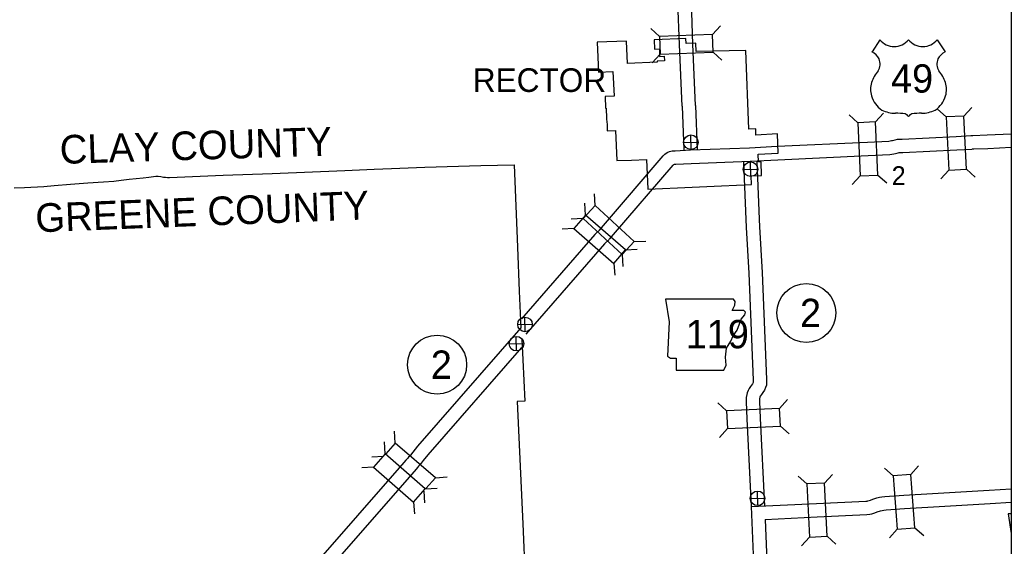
# Model space of a CAD drawing. Extents: x -0.3 to 2.65, y 0 to 1.9.
# Drawn here: x 0.1338 to 0.3417, y 0.6874 to 0.7976 of the extents above; entities that cross this region are included whole.
import ezdxf

# ---------------------------------------------------------------- set-up
doc = ezdxf.new("R2010")
doc.units = 0
for name, color, linetype in [('DSN_DRFT_DNC', 7, 'Continuous'), ('Level 10', 7, 'Continuous'), ('Level 21', 7, 'Continuous'), ('Level 22', 7, 'Continuous'), ('Level 23', 7, 'Continuous'), ('Level 26', 7, 'Continuous'), ('Level 27', 7, 'Continuous'), ('Level 38', 7, 'Continuous'), ('Level 39', 7, 'Continuous'), ('Level 59', 7, 'Continuous'), ('Level 6', 7, 'Continuous')]:
    doc.layers.add(name, color=color, linetype=linetype)

msp = doc.modelspace()

# ---------------------------------------------------------------- linework, layer by layer
at = {"layer": 'DSN_DRFT_DNC'}
msp.add_lwpolyline([(0.04166666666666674, 0.8750000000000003), (0.34166666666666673, 0.8750000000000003), (0.34166666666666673, 0.541666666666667), (0.04166666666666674, 0.541666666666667)], close=True, dxfattribs=at)
at = {"layer": 'Level 21'}
for p, q in [((0.3370799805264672, 0.6990997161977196), (0.34166666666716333, 0.6993791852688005)), ((0.3372510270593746, 0.6962924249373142), (0.34166666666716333, 0.6965614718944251))]:
    msp.add_line(p, q, dxfattribs=at)
for points in [[(0.2726580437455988, 0.7795435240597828), (0.272141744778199, 0.7924518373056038), (0.2718029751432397, 0.8012743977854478)], [(0.27546828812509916, 0.7796559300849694), (0.2749520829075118, 0.7925619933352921), (0.27461354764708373, 0.8013784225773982)], [(0.2726580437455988, 0.7795435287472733), (0.27302461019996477, 0.7703786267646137)], [(0.27546828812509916, 0.7796559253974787), (0.27583518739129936, 0.7704826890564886)], [(0.2855585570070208, 0.7678157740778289), (0.28611326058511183, 0.7541116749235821)], [(0.28836677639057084, 0.7679783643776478), (0.28892345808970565, 0.7542254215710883)], [(0.28611416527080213, 0.754092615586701), (0.2866308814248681, 0.7445370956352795), (0.2875687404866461, 0.7221638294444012), (0.28758491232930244, 0.721813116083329), (0.2875783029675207, 0.7217379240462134), (0.2875546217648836, 0.7216719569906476), (0.2874399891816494, 0.721405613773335), (0.28725100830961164, 0.7211120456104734), (0.28702914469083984, 0.7207873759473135), (0.28673953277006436, 0.7203925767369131), (0.2864928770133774, 0.7199808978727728), (0.28630370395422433, 0.7195135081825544), (0.2862182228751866, 0.7191054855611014), (0.28611414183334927, 0.7184821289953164), (0.2861087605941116, 0.7176244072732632), (0.2862352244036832, 0.714059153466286), (0.28711901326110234, 0.6956487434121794)], [(0.28892255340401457, 0.7542444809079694), (0.28944019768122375, 0.7446719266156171), (0.29037851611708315, 0.7222875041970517), (0.29040309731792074, 0.7217545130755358), (0.29034817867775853, 0.7211296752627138), (0.29017236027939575, 0.7206399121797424), (0.289931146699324, 0.7200794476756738), (0.28959493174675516, 0.7195571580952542), (0.2893247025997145, 0.7191617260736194), (0.2890847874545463, 0.7188346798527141), (0.2890178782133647, 0.7187230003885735), (0.28900495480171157, 0.718691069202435), (0.28898280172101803, 0.7185853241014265), (0.28892517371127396, 0.7182401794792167), (0.28892156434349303, 0.7176654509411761), (0.2890453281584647, 0.7141764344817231), (0.2899288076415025, 0.6957724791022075)], [(0.28712597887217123, 0.6956467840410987), (0.30087906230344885, 0.6963295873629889), (0.3112075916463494, 0.6967827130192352), (0.3114881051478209, 0.6968142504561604), (0.31164821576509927, 0.6968562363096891), (0.31216593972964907, 0.6970312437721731), (0.31268421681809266, 0.6972220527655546), (0.3135328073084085, 0.697480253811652), (0.3140553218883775, 0.6976040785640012), (0.3145580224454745, 0.6976969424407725), (0.31518413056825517, 0.6977582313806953), (0.3191289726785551, 0.6980559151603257), (0.32518447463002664, 0.6984041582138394), (0.33708341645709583, 0.6990999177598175)], [(0.2900566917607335, 0.6929763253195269), (0.30101042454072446, 0.6935201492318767), (0.31142660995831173, 0.6939771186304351), (0.3120046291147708, 0.6940421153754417), (0.31245621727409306, 0.6941605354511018), (0.3131022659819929, 0.694378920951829), (0.3135801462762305, 0.6945548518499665), (0.3142671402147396, 0.6947638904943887), (0.31463539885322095, 0.6948511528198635), (0.3149511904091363, 0.6949094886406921), (0.3154269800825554, 0.6949560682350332), (0.3193155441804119, 0.6952495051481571), (0.3253472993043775, 0.6955963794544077), (0.33724759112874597, 0.6962922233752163)], [(0.28712597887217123, 0.6956467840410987), (0.28799091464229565, 0.6755768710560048), (0.2882637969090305, 0.6694553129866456)], [(0.2900561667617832, 0.6929763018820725), (0.2908007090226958, 0.6757000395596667), (0.2910734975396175, 0.6695805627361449)]]:
    msp.add_lwpolyline(points, dxfattribs=at)
at = {"layer": 'Level 22'}
msp.add_lwpolyline([(0.2692183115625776, 0.739145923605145), (0.26993203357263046, 0.7343877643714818), (0.26961482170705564, 0.7271712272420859), (0.2702492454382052, 0.7267747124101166), (0.27143878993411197, 0.7267747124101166), (0.27143878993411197, 0.7242370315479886), (0.2814309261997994, 0.7242370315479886), (0.28190673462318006, 0.7252679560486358), (0.281748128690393, 0.7269333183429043), (0.28198603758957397, 0.7288365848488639), (0.2828583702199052, 0.730343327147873), (0.283413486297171, 0.7314535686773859), (0.28420651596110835, 0.7326431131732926), (0.2846823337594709, 0.7339119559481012), (0.28507884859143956, 0.734942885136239), (0.2857925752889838, 0.7358152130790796), (0.2859511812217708, 0.7363703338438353), (0.285633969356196, 0.7367668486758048), (0.28317558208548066, 0.7367668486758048), (0.2837306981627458, 0.7378770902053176), (0.2838100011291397, 0.7385908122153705), (0.2834811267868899, 0.7391389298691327)], close=True, dxfattribs=at)
msp.add_lwpolyline([(0.3416666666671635, 0.6941333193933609), (0.3410443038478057, 0.6941336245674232), (0.34166666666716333, 0.6899845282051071)], dxfattribs=at)
at = {"layer": 'Level 23'}
for points in [[(0.16086406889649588, 0.7646429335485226), (0.16235440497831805, 0.7648591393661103), (0.16281201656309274, 0.7649075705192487), (0.16340873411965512, 0.7647831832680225), (0.16397693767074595, 0.7646669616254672), (0.16439109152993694, 0.7646381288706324), (0.16474906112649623, 0.7646068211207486), (0.1651713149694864, 0.7646066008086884), (0.17642949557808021, 0.7650652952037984), (0.18670563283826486, 0.7654524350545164), (0.201991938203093, 0.7660604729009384), (0.20809737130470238, 0.766339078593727), (0.2117773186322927, 0.7665107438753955), (0.21871064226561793, 0.7667410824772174), (0.23047998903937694, 0.7670998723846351), (0.2374720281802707, 0.7672762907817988), (0.23817552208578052, 0.7500029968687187)], [(0.13264490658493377, 0.7624142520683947), (0.1347763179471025, 0.7625336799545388), (0.13887330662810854, 0.7626916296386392), (0.1409924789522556, 0.7628953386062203), (0.14442978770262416, 0.7631720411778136), (0.14804485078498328, 0.7634547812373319), (0.1513627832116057, 0.7636615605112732), (0.15351001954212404, 0.7638662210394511), (0.155048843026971, 0.7640596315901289), (0.15674606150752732, 0.7642772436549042), (0.15965947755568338, 0.7645361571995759), (0.16086406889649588, 0.7646429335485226)], [(0.23817552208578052, 0.7500029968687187), (0.23849075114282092, 0.740757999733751), (0.23887282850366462, 0.7330998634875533)], [(0.23907959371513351, 0.7307290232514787), (0.23972831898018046, 0.7177264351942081), (0.23808092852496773, 0.717649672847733), (0.23929112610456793, 0.6920143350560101), (0.2397868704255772, 0.6804493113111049), (0.24017406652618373, 0.6714418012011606), (0.24039522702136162, 0.6670523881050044), (0.2650557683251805, 0.6682768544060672), (0.2874486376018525, 0.6694059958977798)]]:
    msp.add_lwpolyline(points, dxfattribs=at)
at = {"layer": 'Level 26'}
for p, q in [((0.31411140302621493, 0.7934594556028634), (0.3124887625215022, 0.7909500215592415)), ((0.32617612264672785, 0.7934594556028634), (0.3277987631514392, 0.7909500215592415))]:
    msp.add_line(p, q, dxfattribs=at)
for centre, radius, start, end in [((0.31713325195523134, 0.7960018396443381), 0.0039490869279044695, 220.0750416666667, 319.6701166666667), ((0.3231542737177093, 0.7960018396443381), 0.003949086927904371, 220.32988333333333, 319.92495833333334), ((0.31036849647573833, 0.7873070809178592), 0.00421571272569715, 30.780902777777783, 59.98827222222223), ((0.329919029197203, 0.7873070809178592), 0.00421571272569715, 120.01172777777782, 149.21909722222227), ((0.31129612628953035, 0.7884188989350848), 0.002889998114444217, 328.8104583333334, 21.210766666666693), ((0.32899139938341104, 0.7884188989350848), 0.0028899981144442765, 158.78923333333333, 211.18954166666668), ((0.3188533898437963, 0.7824951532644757), 0.006742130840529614, 138.9564777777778, 162.69134722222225), ((0.32143413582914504, 0.7824951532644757), 0.006742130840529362, 17.308652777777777, 41.04352222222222), ((0.31662772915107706, 0.7830475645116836), 0.004454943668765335, 160.95764444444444, 197.38185555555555), ((0.3236597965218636, 0.7830475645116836), 0.004454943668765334, 342.61814444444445, 19.042355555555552), ((0.3173529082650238, 0.7830602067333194), 0.005154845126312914, 195.10743055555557, 237.13119444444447), ((0.3229346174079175, 0.7830602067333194), 0.005154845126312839, 302.8688055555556, 344.89256944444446), ((0.31744894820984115, 0.7846837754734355), 0.00661920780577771, 244.07708333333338, 269.5778527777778), ((0.3176020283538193, 0.7659415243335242), 0.01212490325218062, 81.19415555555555, 90.953875), ((0.31911823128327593, 0.7768125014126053), 0.0011618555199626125, 28.034222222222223, 72.98637222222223), ((0.3211692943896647, 0.7768125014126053), 0.0011618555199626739, 107.01362777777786, 151.96577777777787), ((0.32268549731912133, 0.7659415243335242), 0.012124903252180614, 89.04612500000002, 98.80584444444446), ((0.3228385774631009, 0.7846837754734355), 0.0066192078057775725, 270.42214722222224, 295.92291666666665)]:
    msp.add_arc(centre, radius, start, end, dxfattribs=at)
at = {"layer": 'Level 27'}
for points in [[(0.2553620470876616, 0.7535983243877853), (0.25622183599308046, 0.7545319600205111), (0.26872967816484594, 0.7691348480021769), (0.2690859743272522, 0.769470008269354), (0.26954757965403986, 0.7698277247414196), (0.27006157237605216, 0.7700253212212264), (0.27061111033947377, 0.7701702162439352), (0.27122311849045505, 0.7702095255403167), (0.27442531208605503, 0.7703791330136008), (0.286837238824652, 0.7708321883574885), (0.2925970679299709, 0.7711425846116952), (0.3115590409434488, 0.7720068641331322), (0.3159874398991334, 0.7722486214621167), (0.31656468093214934, 0.7723206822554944), (0.31678781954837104, 0.7723729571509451), (0.3173346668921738, 0.7725022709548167), (0.3178282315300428, 0.7726115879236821), (0.31880820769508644, 0.7726655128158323), (0.3301031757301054, 0.7732200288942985), (0.33330448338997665, 0.7733800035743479)], [(0.33323498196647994, 0.7733748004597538), (0.3336395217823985, 0.7734151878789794), (0.3366521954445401, 0.773513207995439), (0.34166666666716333, 0.7737541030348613)], [(0.25743091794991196, 0.7516930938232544), (0.2583249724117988, 0.7526639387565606), (0.2707671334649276, 0.7671901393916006), (0.27091506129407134, 0.7673292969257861), (0.27093940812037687, 0.7673481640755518), (0.2710640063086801, 0.7673810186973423), (0.27138764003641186, 0.7674018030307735), (0.2745509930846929, 0.7675693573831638), (0.2869642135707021, 0.7680224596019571), (0.29273677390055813, 0.7683335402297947), (0.3116997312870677, 0.7691978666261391), (0.31623860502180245, 0.7694456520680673), (0.31706102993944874, 0.7695483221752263), (0.31743219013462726, 0.7696352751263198), (0.3179623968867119, 0.7697606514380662), (0.31821212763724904, 0.769815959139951), (0.31895442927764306, 0.7698568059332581), (0.3302423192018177, 0.7704109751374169), (0.33344485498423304, 0.7705710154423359)], [(0.33351435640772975, 0.7705762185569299), (0.33382514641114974, 0.7706072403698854), (0.33676540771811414, 0.7707029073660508), (0.34166666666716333, 0.7709383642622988)], [(0.25541840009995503, 0.7536560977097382), (0.2543737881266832, 0.7526448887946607), (0.2389892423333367, 0.735011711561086)], [(0.2573745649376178, 0.7516353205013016), (0.2564151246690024, 0.7507065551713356), (0.23990041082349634, 0.7317780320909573)], [(0.23887062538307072, 0.7330997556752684), (0.21717789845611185, 0.7082877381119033), (0.2162002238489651, 0.7070598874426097), (0.215723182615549, 0.7064492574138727), (0.21556655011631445, 0.7062432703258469), (0.21533925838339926, 0.7059993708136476), (0.21507742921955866, 0.7057086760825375), (0.2147759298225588, 0.7053534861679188), (0.21434821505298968, 0.7048591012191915), (0.16674346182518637, 0.6504592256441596), (0.1664469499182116, 0.6500967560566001), (0.16619319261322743, 0.6497620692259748), (0.16608823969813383, 0.6496233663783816), (0.16590203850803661, 0.6494166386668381), (0.1656448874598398, 0.6489837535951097), (0.16548952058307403, 0.648699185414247), (0.1653403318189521, 0.6484147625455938), (0.1650963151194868, 0.6479254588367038), (0.16506586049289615, 0.6474507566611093)], [(0.23901848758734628, 0.7289958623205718), (0.21933782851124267, 0.7064852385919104), (0.21840854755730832, 0.7053181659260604), (0.21795083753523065, 0.7047322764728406), (0.2177200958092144, 0.7044288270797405), (0.21741306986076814, 0.7040993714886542), (0.217194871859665, 0.7038571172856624), (0.21691155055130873, 0.7035233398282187), (0.21646997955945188, 0.7030129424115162), (0.16889076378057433, 0.6486422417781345), (0.16865672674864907, 0.6483561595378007), (0.16843516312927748, 0.648063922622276), (0.16825847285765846, 0.6478304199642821), (0.1681779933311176, 0.6477410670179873), (0.16808897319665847, 0.6475912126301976), (0.1679692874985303, 0.6473719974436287), (0.1678665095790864, 0.6471760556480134), (0.16783376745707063, 0.6466657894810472)]]:
    msp.add_lwpolyline(points, dxfattribs=at)
at = {"layer": 'Level 38'}
for p, q in [((0.27903702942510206, 0.7945842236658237), (0.2807157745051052, 0.7964028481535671)), ((0.2679084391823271, 0.7941391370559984), (0.26608981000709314, 0.7958178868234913)), ((0.26805679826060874, 0.7904296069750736), (0.2663780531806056, 0.7886109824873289)), ((0.2791853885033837, 0.7908746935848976), (0.28100401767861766, 0.7891959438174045)), ((0.30952150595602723, 0.776080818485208), (0.30769354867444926, 0.7777494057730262)), ((0.3132301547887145, 0.7762498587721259), (0.3148987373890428, 0.778077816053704)), ((0.32804567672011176, 0.7772865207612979), (0.32621188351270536, 0.7789486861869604)), ((0.3317537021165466, 0.7774685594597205), (0.33341586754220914, 0.7793023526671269)), ((0.3100286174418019, 0.7649548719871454), (0.3083600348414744, 0.7631269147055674)), ((0.31373726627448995, 0.7651239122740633), (0.3155652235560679, 0.7634553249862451)), ((0.328591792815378, 0.7661624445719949), (0.3269296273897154, 0.7643286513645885)), ((0.3322998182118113, 0.7663444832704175), (0.33413361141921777, 0.7646823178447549)), ((0.2544344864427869, 0.7587357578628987), (0.25433266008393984, 0.7612086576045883)), ((0.25241864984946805, 0.7567354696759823), (0.25225047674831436, 0.7592047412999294)), ((0.2519195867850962, 0.756004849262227), (0.24944668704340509, 0.7559030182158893)), ((0.24997796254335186, 0.7539380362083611), (0.24750869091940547, 0.7537698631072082)), ((0.2626272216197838, 0.7511910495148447), (0.26510012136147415, 0.7512928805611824)), ((0.2601123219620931, 0.748460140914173), (0.2602141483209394, 0.7459872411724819)), ((0.2608109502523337, 0.7494134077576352), (0.2632802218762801, 0.7495815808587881)), ((0.2583702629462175, 0.746615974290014), (0.2585384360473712, 0.744146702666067)), ((0.2819889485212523, 0.7157048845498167), (0.28015696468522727, 0.7173690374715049)), ((0.2931135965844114, 0.716238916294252), (0.2947777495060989, 0.7180709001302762)), ((0.21252024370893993, 0.7089765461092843), (0.21234176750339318, 0.711445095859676)), ((0.2821669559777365, 0.7119966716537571), (0.28050280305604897, 0.7101646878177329)), ((0.2932916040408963, 0.7125307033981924), (0.29512358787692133, 0.7108665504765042)), ((0.2104460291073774, 0.7067206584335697), (0.21028152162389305, 0.7091901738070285)), ((0.21252024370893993, 0.7089765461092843), (0.21054297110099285, 0.7066910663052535)), ((0.2209430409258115, 0.7016895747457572), (0.21252024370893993, 0.7089765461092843)), ((0.21009125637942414, 0.7061689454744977), (0.20762270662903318, 0.7059904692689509)), ((0.2080011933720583, 0.7039268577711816), (0.20553167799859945, 0.7037623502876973)), ((0.31695224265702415, 0.7020659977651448), (0.3150754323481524, 0.7036794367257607)), ((0.32065422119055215, 0.7023453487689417), (0.3222676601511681, 0.7042221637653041)), ((0.21897784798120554, 0.6994180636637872), (0.2209430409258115, 0.7016895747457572)), ((0.2209430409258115, 0.7016895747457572), (0.22341159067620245, 0.7018680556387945)), ((0.29881463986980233, 0.7003947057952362), (0.2969799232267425, 0.7020558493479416)), ((0.30252256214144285, 0.7005787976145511), (0.3041837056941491, 0.7024135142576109)), ((0.2185140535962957, 0.6988819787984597), (0.21869252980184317, 0.6964134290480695)), ((0.21882744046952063, 0.6993861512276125), (0.22129695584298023, 0.6995506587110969)), ((0.21638260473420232, 0.6965923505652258), (0.21654711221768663, 0.6941228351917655)), ((0.3177902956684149, 0.6909600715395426), (0.316176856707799, 0.6890832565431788)), ((0.3214922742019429, 0.6912394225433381), (0.3233690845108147, 0.6896259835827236)), ((0.29936692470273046, 0.6892709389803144), (0.2977057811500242, 0.6874362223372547)), ((0.303074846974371, 0.6894550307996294), (0.3049095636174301, 0.6877938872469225))]:
    msp.add_line(p, q, dxfattribs=at)
for points in [[(0.26805679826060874, 0.7904296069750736), (0.2791853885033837, 0.7908746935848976), (0.27903702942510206, 0.7945842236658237), (0.2679084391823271, 0.7941391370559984)], [(0.32804567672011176, 0.7772865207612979), (0.328591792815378, 0.7661624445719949), (0.3322998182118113, 0.7663444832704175), (0.3317537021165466, 0.7774685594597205)], [(0.30952150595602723, 0.776080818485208), (0.3100286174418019, 0.7649548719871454), (0.31373726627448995, 0.7651239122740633), (0.3132301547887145, 0.7762498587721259)], [(0.2519195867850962, 0.756004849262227), (0.2601123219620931, 0.748460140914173), (0.2626272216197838, 0.7511910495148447), (0.2544344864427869, 0.7587357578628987)], [(0.24997796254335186, 0.7539380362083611), (0.2583702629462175, 0.746615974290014), (0.2608109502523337, 0.7494134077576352), (0.25241864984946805, 0.7567354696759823)], [(0.2821669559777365, 0.7119966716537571), (0.2932916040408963, 0.7125307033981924), (0.2931135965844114, 0.716238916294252), (0.2819889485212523, 0.7157048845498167)], [(0.2080011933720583, 0.7039268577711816), (0.21638260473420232, 0.6965923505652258), (0.21882744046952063, 0.6993861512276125), (0.2104460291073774, 0.7067206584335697)], [(0.29881463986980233, 0.7003947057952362), (0.29936692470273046, 0.6892709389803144), (0.303074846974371, 0.6894550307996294), (0.30252256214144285, 0.7005787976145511)], [(0.31695224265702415, 0.7020659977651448), (0.3177902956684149, 0.6909600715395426), (0.3214922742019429, 0.6912394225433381), (0.32065422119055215, 0.7023453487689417)]]:
    msp.add_lwpolyline(points, close=True, dxfattribs=at)
at = {"layer": 'Level 39'}
for p, q in [((0.2745605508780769, 0.7704648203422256), (0.274490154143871, 0.7735161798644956)), ((0.27299967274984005, 0.7719553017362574), (0.27605103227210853, 0.7720256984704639)), ((0.28706858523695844, 0.7648192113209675), (0.28699818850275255, 0.767870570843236)), ((0.2855077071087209, 0.7663096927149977), (0.2885590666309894, 0.7663800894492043)), ((0.23820793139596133, 0.7337788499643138), (0.24125929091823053, 0.7338492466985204)), ((0.23976880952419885, 0.7322883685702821), (0.239698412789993, 0.7353397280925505)), ((0.2364096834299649, 0.7297482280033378), (0.2394610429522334, 0.7298186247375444)), ((0.23797056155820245, 0.7282577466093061), (0.23790016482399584, 0.7313091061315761)), ((0.2885318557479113, 0.6958623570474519), (0.28846145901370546, 0.6989137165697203)), ((0.2869709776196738, 0.6973528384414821), (0.290022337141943, 0.6974232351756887))]:
    msp.add_line(p, q, dxfattribs=at)
for centre in [(0.2745253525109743, 0.7719905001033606), (0.28703338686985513, 0.766344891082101), (0.2397336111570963, 0.7338140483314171), (0.23793536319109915, 0.7297834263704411), (0.2884966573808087, 0.6973880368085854)]:
    msp.add_circle(centre, 0.0015260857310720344, dxfattribs=at)
at = {"layer": 'Level 59'}
for centre in [(0.29871051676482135, 0.7362204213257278), (0.22131766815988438, 0.7253853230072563)]:
    msp.add_circle(centre, 0.006187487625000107, dxfattribs=at)
at = {"layer": 'Level 6'}
msp.add_lwpolyline([(0.2747822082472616, 0.7625891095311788), (0.2809218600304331, 0.7628742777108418), (0.28722363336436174, 0.7631669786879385), (0.2871460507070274, 0.76493968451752), (0.2893254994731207, 0.7649904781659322), (0.2892194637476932, 0.7678947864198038), (0.2886962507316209, 0.7678825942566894), (0.28861531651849, 0.7694971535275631), (0.29284777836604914, 0.7696951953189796), (0.29264925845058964, 0.77371811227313), (0.28814770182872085, 0.7734568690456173), (0.28813599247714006, 0.7747717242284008), (0.2866989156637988, 0.7747057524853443), (0.28606498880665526, 0.7912303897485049), (0.2756419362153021, 0.7910293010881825), (0.27557122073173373, 0.7927569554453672), (0.2735106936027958, 0.7926669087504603), (0.273467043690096, 0.7937232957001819), (0.2668214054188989, 0.7934411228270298), (0.26690387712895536, 0.7915140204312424), (0.2679121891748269, 0.7915593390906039), (0.2679617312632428, 0.7899493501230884), (0.2689463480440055, 0.7899936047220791), (0.2689911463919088, 0.7890640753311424), (0.2674168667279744, 0.7890005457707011), (0.26742597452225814, 0.7887877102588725), (0.26119275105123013, 0.7885039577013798), (0.26098515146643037, 0.7931933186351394), (0.25486854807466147, 0.7929220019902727), (0.2551368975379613, 0.7866927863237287), (0.25818558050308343, 0.7868201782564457), (0.2584002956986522, 0.781643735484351), (0.2565113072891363, 0.7815945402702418), (0.2565827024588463, 0.779145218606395), (0.2567378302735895, 0.7791500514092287), (0.2568262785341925, 0.7769929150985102), (0.2568915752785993, 0.7761290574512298), (0.25693664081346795, 0.7758474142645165), (0.2569674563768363, 0.7754794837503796), (0.256981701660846, 0.7752390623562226), (0.2569591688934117, 0.7747884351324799), (0.25697042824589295, 0.7743717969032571), (0.2586990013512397, 0.774442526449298), (0.25896052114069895, 0.7681378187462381), (0.26209097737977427, 0.768214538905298), (0.2651921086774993, 0.7683678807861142), (0.2654863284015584, 0.76215733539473)], close=True, dxfattribs=at)

# ---------------------------------------------------------------- texts
at = {"layer": 'Level 10'}
for s, height, rotation, p in [('CLAY COUNTY', 0.005999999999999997, 1.7725208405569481, (0.14227718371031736, 0.7674410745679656)), ('GREENE COUNTY', 0.005999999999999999, 2.2372212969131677, (0.13718625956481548, 0.753104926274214))]:
    msp.add_text(s, height=height, rotation=rotation, dxfattribs=at).set_placement(p)
at = {"layer": 'Level 22'}
msp.add_text('119', height=0.005939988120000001, dxfattribs=at).set_placement((0.2734220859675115, 0.7288200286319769))
at = {"layer": 'Level 26'}
msp.add_text('49', height=0.005939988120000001, dxfattribs=at).set_placement((0.3164690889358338, 0.7823839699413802))
at = {"layer": 'Level 38'}
msp.add_text('2', height=0.00395999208, dxfattribs=at).set_placement((0.3166093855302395, 0.763001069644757))
at = {"layer": 'Level 59'}
for p in [(0.29738178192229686, 0.7332504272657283), (0.21998893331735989, 0.7224153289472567)]:
    msp.add_text('2', height=0.005939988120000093, dxfattribs=at).set_placement(p)
at = {"layer": 'Level 6'}
msp.add_text('RECTOR', height=0.004949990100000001, dxfattribs=at).set_placement((0.2287936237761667, 0.7825283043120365))

doc.saveas('drawing.dxf')
